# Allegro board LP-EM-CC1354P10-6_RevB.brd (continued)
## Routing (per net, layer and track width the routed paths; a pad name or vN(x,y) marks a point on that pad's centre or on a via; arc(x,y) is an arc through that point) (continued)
DIO35: length 25.9
  TOP w0.15: v1(30.61,49.53) 30.61,49.46 30.75,49.32 U1.11 ; v1(33.22,48.96) 33.41,48.96 33.7,49.25 34.38,49.25 34.48,49.15 35.61,49.15 35.63,49.12 35.99,49.12 36.06,49.2 R18.2
  L3 w0.15: P5.2 48.26,40.76 47.7,41.32 47.22,41.32 40.87,47.68 38.32,47.68 37.88,48.12 35.38,48.12 34.66,48.84 34.66,48.84 34.41,49.09 34.41,49.09 34.3,49.2 33.46,49.2 v1(33.22,48.96)
  BOTTOM w0.15: v1(33.22,48.96) 31.18,48.96 v1(30.61,49.53)
DIO35_RF_SUB1G: length 19.5
  TOP w0.15: v1(36.75,48.67) 36.75,48.8 36.9,48.95 R18.1 ; U2.6 v1(29.33,38.35)
  L3 w0.15: v1(29.33,38.35) 30.1,38.35 30.52,38.76 30.53,38.76 30.76,38.99 30.76,39 30.78,39.03 30.78,39.36 31.47,40.05 31.47,41.65 32.98,43.15 32.98,45.32 33.04,45.38 33.04,46.71 32.31,47.44 32.31,47.47 32.3,47.48 32.3,49.07 33.07,49.85 34.5,49.85 34.66,49.69 34.66,49.69 35.23,49.12 36.3,49.12 v1(36.75,48.67)
DIO36_FLASH_MOSI: length 79.9
  TOP w0.15: U3.5 35.45,71.43 v1(37.67,71.43) ; U1.22 34.04,51.6 34.22,51.78 35.24,51.78 35.34,51.88 38.17,51.88 38.23,51.82 38.26,51.82 38.38,51.69 38.74,51.69 38.86,51.82 40.11,51.82 40.65,51.28 41.4,51.28 41.67,51.55 v1(41.7,51.55) 41.7,58.8 v1(41.9,59)
  L3 w0.15: v1(41.9,59) 37.85,63.05 33.93,63.05 30.3,66.68 30.3,68.4 31.2,69.3 38.88,69.3 39.9,70.32 39.9,71.01 39.46,71.45 38.35,71.45 38.32,71.43 v1(37.67,71.43) ; v1(41.7,51.55) 41.67,51.53 41.67,51.25 41.57,51.15 41.57,49.1 47.85,42.82 49.25,42.82 50.67,41.4 50.67,39.22 49.8,38.35 49.8,34.93 48.95,34.07 45.6,34.07 44.42,35.25 44.42,36.68 P5.3
DIO37_FLASH_MISO: length 56
  TOP w0.15: U3.2 v1(32.27,72.65) ; v1(40.85,51.7) 40.44,52.11 40.34,52.11 40.33,52.12 v1(38.56,52.12) 38.36,52.12 38.3,52.18 35.22,52.18 35.12,52.07 34.09,52.07 34.02,52 U1.23
  L3 w0.15: v1(38.56,52.12) 38.47,52.2 38.47,52.26 38.35,52.38 38.35,52.7 38.46,52.81 38.46,52.86 38.47,52.87 38.52,52.92 38.52,55.53 36.48,57.57 35.55,57.57 33.57,59.55 33.57,59.55 27.6,65.53 27.6,69.53 30.72,72.65 v1(32.27,72.65) ; v1(40.85,51.7) 40.92,51.62 40.92,48.9 47.6,42.22 49,42.22 50.07,41.15 50.07,39.47 48.58,37.98 P5.4
DIO38_FLASH_CS: length 66.3
  TOP w0.15: v1(31.22,73.15) R24.1 U3.1 ; U1.24 35.02,52.4 35.09,52.47 38.31,52.47 38.38,52.54 38.79,52.54 38.88,52.62 38.88,52.62 v1(38.89,52.63) 39.07,52.45 40.42,52.45 40.46,52.41 40.99,52.41 41.05,52.35 v1(41.22,52.35)
  L3 w0.15: v1(31.22,73.15) 32.38,73.15 32.7,72.83 32.7,72.47 32.41,72.19 30.69,72.19 27.9,69.4 27.9,65.65 33.88,59.68 33.88,59.67 35.67,57.88 36.61,57.88 38.89,55.59 v1(38.89,52.63) ; v1(41.22,52.35) 41.22,52.2 41.21,52.19 41.21,52.16 41.27,52.1 41.27,48.97 47.72,42.53 49.12,42.53 50.38,41.28 50.38,39.35 49.47,38.45 49.47,35.03 48.82,34.38 46.45,34.38 45.72,35.1 P5.5
DIO39_FLASH_SCLK: length 70.8
  TOP w0.15: U3.6 35.88,72.15 36.02,72 v1(36.02,71.95) ; U1.25 38.21,52.8 38.49,53.07 39.08,53.07 39.23,52.93 40.55,52.93 v1(40.64,52.84) 40.72,52.93 40.72,57.65 40.55,57.82 v1(40.55,59.2)
  L3 w0.15: v1(40.64,52.84) 40.52,52.72 40.52,51.98 40.51,51.96 40.51,51.96 40.42,51.87 40.42,51.52 40.52,51.42 40.52,48.87 47.47,41.93 48.88,41.93 49.77,41.03 49.77,39.6 49.2,39.03 47.38,39.03 47.07,38.72 47.07,36.9 48.26,35.71 P5.6 ; v1(40.55,59.2) 40.55,59.65 37.45,62.75 33.8,62.75 30,66.55 30,68.53 31.07,69.6 37.62,69.6 38.22,70.2 39.35,70.2 39.6,70.45 39.6,70.88 39.33,71.15 38.47,71.15 38.33,71.01 37.86,71.01 37.85,71 37.5,71 37.49,71.01 36.17,71.01 36.02,71.15 v1(36.02,71.95)
DIO40: length 39.4
  TOP w0.15: R10.2 R8.2 39.17,69.95 v1(39.17,70.71) ; U1.41 29.55,57.2 30.6,58.25 30.6,58.72 31.15,59.28 31.15,59.3 31.4,59.55 32.52,59.55 33.8,60.82 v1(34.42,60.82)
  L3 w0.15: v1(39.17,70.71) 37.98,70.71 37.98,70.7 36,70.7 35.2,69.9 30.95,69.9 29.7,68.65 29.7,66.43 33.68,62.45 37.32,62.45 38.55,61.22 38.55,59.9 38.3,59.65 37.01,59.65 36.56,60.1 36.52,60.1 36.15,60.47 34.77,60.47 v1(34.42,60.82)
DIO41: length 42.9
  TOP w0.15: v1(32.77,55.68) 31.95,55.68 31.82,55.8 29.36,55.8 29.15,56.01 U1.42
  L3 w0.15: v1(32.77,55.68) 34.92,55.68 35.38,55.22 35.38,54.03 36.97,52.43 36.97,50.48 38.85,48.6 39.48,48.6 39.9,49.02 39.9,51.13 39.79,51.24 39.79,52.08 39.91,52.21 39.91,53.14 40.42,53.65 41.07,53.65 43.32,51.4 43.32,49.35 48.47,44.2 52.25,44.2 53.12,45.07 53.12,47.09 J2.18
DIO42: length 46.7
  TOP w0.15: U1.43 28.75,55.92 29.17,55.5 31.07,55.5 v1(31.2,55.38)
  L3 w0.15: v1(31.2,55.38) 31.32,55.25 32.94,55.25 33.03,55.34 34.81,55.34 35.07,55.07 35.07,53.9 36.67,52.3 36.67,50.35 38.73,48.3 39.6,48.3 40.2,48.9 40.2,51.25 40.12,51.33 40.12,51.4 40.09,51.44 40.09,51.96 40.21,52.08 40.21,53.01 40.55,53.35 40.95,53.35 43.02,51.28 43.02,49.22 48.35,43.9 52.38,43.9 53.42,44.95 53.42,49.18 52.07,50.53 J2.16
DIO43: length 27.8
  TOP w0.15: U1.44 28.35,55.88 28.6,55.63 v1(28.6,55.45)
  L3 w0.15: v1(28.6,55.45) 28.6,55.5 28.42,55.68 27.77,55.68 27.52,55.43 27.52,55.42 27.27,55.17 27.27,50.18 25.75,48.65 25,48.65 24,49.65 22.79,49.65 21.64,48.5 9.23,48.5 J1.18
DIO44: length 28.5
  TOP w0.15: v1(27.95,55.25) U1.45
  L3 w0.15: v1(27.95,55.25) 27.6,54.9 27.6,49.3 26.05,47.75 24.7,47.75 23.63,48.82 22.75,48.82 22.7,48.77 22.68,48.77 19.41,45.5 8.97,45.5 J1.20
DIO45: length 61.1
  TOP w0.15: v1(34.11,56.11) 34.92,56.93 36.1,56.93 v1(37.7,58.53) ; R19.1 25.07,56.3 25.95,56.3 v1(25.97,56.28) 26.07,56.28 26.65,55.7 27.23,55.7 27.55,56.02 U1.46
  L3 w0.15: v1(25.97,56.28) 26.75,57.05 33.17,57.05 v1(34.11,56.11) ; J2.7 41.97,68.4 31.57,68.4 31.2,68.03 31.2,67.05 34.3,63.95 38.4,63.95 42.33,60.03 42.92,59.43 42.92,58.57 42.3,57.95 38.27,57.95 v1(37.7,58.53)
DIO46: length 81.4
  TOP w0.15: v1(19.4,58.1) R20.1 19.52,57.45 19.52,56.5 18.85,55.82 18.85,52.97 19.25,52.57 22.1,52.57 22.7,51.97 23.58,51.97 23.6,52 U1.58
  L3 w0.15: v1(19.4,58.1) 19.52,58.23 19.52,63.15 16.15,66.52 16.15,71.47 17.17,72.5 23.47,72.5 25.95,74.97 28.88,74.97 29.49,74.37 30.76,74.37 30.86,74.46 34.26,74.46 34.54,74.18 39.45,74.18 40.17,74.9 41.6,74.9 42.88,73.62 42.88,70.7 43.55,70.02 45.09,70.02 46.38,71.31 46.38,74.43 47.49,75.54 49.06,75.54 49.48,75.12 49.48,74.76 48.35,73.63 48.35,67.97 49.53,66.79 J2.3
DIO47: length 79.5
  TOP w0.15: U1.59 25.32,51.6 25.3,51.62 23.65,51.62 23.6,51.68 22.57,51.68 21.97,52.28 19.1,52.28 18.55,52.82 18.55,55.95 18.67,56.07 R21.1 18.67,56.82 18.82,56.97 v1(18.95,56.97)
  L3 w0.15: J2.1 49.53,74.39 49.78,74.64 49.78,75.24 49.19,75.84 47.15,75.84 44.89,73.58 44.89,70.72 44.51,70.34 43.67,70.34 43.17,70.83 43.17,73.97 41.9,75.25 40.1,75.25 40.05,75.2 40.05,75.2 39.32,74.47 34.67,74.47 34.38,74.76 30.73,74.76 30.63,74.66 29.61,74.66 28.75,75.53 26.07,75.53 25.82,75.28 25.82,75.28 23.35,72.8 17.05,72.8 15.85,71.6 15.85,66.4 18.95,63.3 v1(18.95,56.97)
LP_RESET: length 17
  TOP w0.15: R10.1 R11.1 v1(42.25,67.5) ; v1(50.95,59.35) 51.02,59.35 J2.10
  L3 w0.15: v1(50.95,59.35) 50.77,59.53 48.44,59.53 42.25,65.72 v1(42.25,67.5)
RX_TX: length 15.2
  TOP w0.15: U1.7 29.15,49.18 28.88,49.45 v1(28.88,49.53)
  TOP w0.3: C56.2 26.28,44.62 v1(26.29,44.61) 26.29,45.07 L40.1 ; 24.3,47.65 23.8,47.65 23.7,47.75 v1(23.65,47.75) ; 24.3,47.65 C11.2 ; 24.3,47.65 L12.1
  L3 w0.3: v1(28.88,49.53) 28.88,48.75 27.77,47.65 ; 27.77,47.65 27.16,47.03 24.41,47.03 23.7,47.75 v1(23.65,47.75) ; 27.77,47.65 27.77,45.1 27.28,44.61 v1(26.29,44.61)
WMCU_RESET: length 95.4
  TOP w0.15: v1(29.27,73.97) 29.27,76.93 29.42,77.07 v1(29.42,77.15) ; v1(49.06,74.94) P6.10 49.06,78.63 50.15,79.72 51.43,79.72 52.52,80.82 52.52,81.65 52.12,82.05 CR2.2 ; U1.49 25.13,55.6 24.7,56.03 24.68,56.03 24.18,56.53 R1.1 23.4,56.53 C54.1 23.1,56.32 22.7,56.72 21.57,56.72 v1(20.55,57.75) ; R9.2 37.95,70.15 37.95,70.5 38.56,71.11 38.98,71.11 39,71.13 39.35,71.13 39.6,70.88 39.6,70.8 39.75,70.65 41.5,70.65 R11.2 42.32,69.83 v1(43.13,69.83)
  L3 w0.15: v1(49.06,74.94) 48.76,75.24 47.61,75.24 46.96,74.6 46.96,70.39 46.3,69.72 43.25,69.72 v1(43.13,69.83) 42.57,70.39 42.57,73.5 41.47,74.6 40.3,74.6 39.57,73.88 34.42,73.88 34.13,74.16 33.81,74.16 33.63,73.97 v1(29.27,73.97) 28.57,74.68 26.07,74.68 23.6,72.2 17.3,72.2 16.45,71.35 16.45,66.65 20.44,62.66 20.44,57.86 v1(20.55,57.75) ; J4.10 30.51,87.01 29.38,85.88 29.38,78.97 29.42,78.93 v1(29.42,77.15)
WMCU_RXD: length 91.2
  TOP w0.15: v1(26.38,77.15) v1(26.38,73.95) ; v1(37.45,53.3) 37.35,53.2 U1.26
  L3 w0.15: J4.14 25.45,87.01 26.5,85.97 26.5,77.28 v1(26.38,77.15) 25.57,77.15 25.2,76.78 25.2,76.78 22.72,74.3 16.42,74.3 15.9,73.78 9.22,73.78 7.38,71.93 7.38,68.03 6.71,67.35 5.85,67.35 4.98,66.48 4.98,65.36 5.77,64.57 5.78,64.57 6.33,64.02 J1.5 ; v1(26.38,73.95) 26.2,73.95 23.85,71.6 17.55,71.6 17.05,71.1 17.05,66.9 21.55,62.4 29.45,62.4 32.07,59.78 32.08,59.78 32.67,59.18 32.67,59.17 35.17,56.68 36.11,56.68 37.45,55.33 v1(37.45,53.3)
WMCU_SWO: length 108.4
  TOP w0.15: v1(34.88,59.4) 33.9,59.4 31.55,57.05 U1.36 ; v1(28.3,73.97) 28.3,76.97 28.42,77.1 v1(28.42,77.22) ; CR3.5 45.11,82.57 44.8,82.27 44.8,79.78 43.27,78.25 43.27,76.97 v1(40.47,74.18)
  L3 w0.15: 34.42,72.97 34.01,73.39 33.81,73.39 33.53,73.68 29.58,73.68 29.38,73.48 29.17,73.48 29.1,73.55 28.67,73.97 v1(28.3,73.97) ; 34.42,72.97 34.42,72.95 33.36,71.88 30.81,71.88 28.2,69.28 28.2,65.78 34.17,59.8 34.17,59.8 34.57,59.4 v1(34.88,59.4) 35.27,59.4 35.37,59.3 35.85,59.3 37.5,57.65 42.43,57.65 43.22,58.45 43.22,59.55 42.45,60.32 42.45,60.32 38.53,64.25 34.43,64.25 31.5,67.18 31.5,67.9 31.7,68.1 38.6,68.1 38.63,68.07 38.92,68.07 48.7,58.3 J2.9 ; 34.42,72.97 35,73.55 35.32,73.55 35.35,73.57 39.88,73.57 v1(40.47,74.18) ; v1(28.42,77.22) 28.27,77.38 28.27,84.18 J4.11
WMCU_TCK: length 68.7
  TOP w0.15: CR2.6 49.9,82.05 v1(49.65,81.8) ; v1(34.7,71) 34.32,70.62 R5.2 ; v1(37.7,60.88) 37.7,60.3 35.54,58.14 34.34,58.14 33.26,57.06 33.26,56.59 33.12,56.45 U1.33 ; v1(41.2,72.93) 41.2,72.98 43.25,75.03 44.63,75.03 45.25,75.64 P6.4 45.25,78.53 45.77,79.05 46.57,79.05 47.47,79.95 47.9,79.95 48.15,80.2 48.15,80.63 48.3,80.78 v1(48.3,81.23)
  L3 w0.15: J4.6 36.76,85.85 38.88,85.85 39.19,85.54 46.51,85.54 48.3,83.75 v1(48.3,81.23) 49.07,81.23 v1(49.65,81.8) ; v1(41.2,72.93) 40.5,72.93 39.75,72.18 36.83,72.18 36.33,72.68 35.72,72.68 34.7,71.65 v1(34.7,71) 34.2,70.5 30.7,70.5 29.1,68.9 29.1,66.18 33.43,61.85 36.85,61.85 37.7,61 v1(37.7,60.88)
WMCU_TMS: length 74
  TOP w0.15: CR2.7 50.15,81.25 v1(49.82,81.25) ; v1(40.95,72) 40.95,72.05 40.62,72.38 40.62,73.44 P6.2 43.98,78.1 45.22,79.35 46.45,79.35 47.39,80.29 47.64,80.29 v1(47.72,80.38) ; U1.32 33.6,56.97 34.47,57.84 35.67,57.84 35.75,57.93 35.8,57.93 37.95,60.07 v1(38.12,60.07) ; R4.2 35.8,70.07 v1(35.22,70.65)
  L3 w0.15: v1(49.82,81.25) 49.41,80.84 48.74,80.84 48.27,80.38 v1(47.72,80.38) 47.72,80.85 47.88,81 47.88,81.83 47.96,81.92 47.96,83.67 46.4,85.23 43.2,85.23 41.4,83.43 40.22,83.43 39.42,84.23 39.42,84.88 38.75,85.55 34.52,85.55 J4.8 ; v1(38.12,60.07) 38.17,60.12 38.17,61.18 37.2,62.15 33.55,62.15 29.4,66.3 29.4,68.78 30.82,70.2 34.77,70.2 v1(35.22,70.65) 35.22,71.75 35.85,72.38 36.2,72.38 36.7,71.88 39.88,71.88 40.35,72.35 40.6,72.35 v1(40.95,72)
WMCU_TXD: length 97
  TOP w0.15: v1(27.35,77.15) 27.35,74 v1(27.3,73.95) ; v1(36.97,53.7) 36.88,53.6 U1.27
  L3 w0.15: J4.12 26.8,85.84 26.8,83.75 27.47,83.07 27.47,77.28 v1(27.35,77.15) 26.92,76.72 25.57,76.72 25.32,76.47 25.32,76.47 22.85,74 16.55,74 16.02,73.47 9.35,73.47 7.68,71.81 7.68,67.63 7.02,66.97 5.9,66.97 5.28,66.35 5.28,65.49 5.9,64.87 6.88,64.87 7.52,64.23 7.52,62.82 7.52,62.82 7.52,62.03 J1.7 ; v1(36.97,53.7) 36.97,55.38 35.98,56.38 35.05,56.38 32.38,59.05 32.38,59.05 31.95,59.47 31.95,59.47 29.32,62.1 21.42,62.1 16.75,66.77 16.75,71.22 17.42,71.9 23.72,71.9 26.2,74.38 26.55,74.38 26.77,74.16 27.15,74.16 27.3,74.01 v1(27.3,73.95)
WMCU_VDD: length 146.6
  TOP w0.15: v1(4.22,47.62) 3.65,47.05 R3.2 ; R2.2 v1(4.18,44.93)
  TOP w0.25: R25.2 33.17,74.53 v1(32.52,75.18) ; R24.2 31.65,73.95 R23.2 v1(30.47,75.05) ; R22.2 v1(38.42,75)
  TOP w0.3: v1(46.12,80.43) CR3.8 ; v1(22.92,60.5) 22.92,60.5 23,60.43 FL1.2 ; v1(43.92,70.82) 43.92,72.89 P6.1 ; v1(51.15,80.65) 51.15,81.4
  L3 w0.15: 4.22,44.97 v1(4.18,44.93)
  L3 w0.5: v1(46.12,80.43) 46.22,80.32 46.22,76.18 ; 51.15,76.2 v1(51.15,80.65) ; 22.89,85.94 J4.16 23.97,87.01 ; v1(43.92,70.82) 43.92,76.18 ; v1(38.42,75) 38.42,76.12 38.38,76.18
  L3 w1: 23.27,82.95 23.52,82.7 v1(23.52,76.18) v1(22.77,76.18) 10.45,76.18 6.33,72.06 J1.1 5.94,68.46 4.22,66.75 4.1,48.55 4.1,47.75 v1(4.22,47.62) 4.22,44.97 ; P3.1 52.34,35.44 54.07,37.17 54.07,43.55 54.92,44.4 54.92,51.82 54.07,52.67 54.07,70.2 51.17,73.1 51.17,76.18 50.7,76.65 46.7,76.65 46.22,76.18 v1(31.8,76.18) v1(31,76.18)
  vias: v1(22.52,60.9) v1(23.17,60.88) v1(23.6,60.6)
XDS_BOARDID_SCL: length 13.6
  TOP w0.15: v1(11.95,83.72) U4.1
  L3 w0.15: J4.15 22.22,84.48 19.88,82.12 13.57,82.12 11.98,83.72 v1(11.95,83.72)
XDS_BOARDID_SDA: length 8.5
  TOP w0.15: v1(13.85,83.72) U4.3
  L3 w0.15: v1(13.85,83.72) 14.65,82.93 18.8,82.93 J4.17
XDS_GPIO1: length 81.3
  TOP w0.15: R19.2 v1(25.26,57.11) ; CR3.1 v1(46.82,81.1)
  L3 w0.15: 38.14,84.47 39.48,83.12 43.25,83.12 44,83.88 44.43,83.88 44.44,83.89 44.76,83.89 44.77,83.88 46.7,83.88 47.38,83.2 47.38,82.78 46.82,82.23 v1(46.82,81.1) ; 38.14,84.47 36.79,83.12 32.27,83.12 32.17,83.02 31.85,83.02 31.35,82.52 31.35,81.93 31,81.58 31,78.08 29.35,76.43 25.7,76.43 25.45,76.18 25.45,76.18 22.97,73.7 16.67,73.7 16.15,73.18 9.47,73.18 8.77,72.48 8.77,71.37 11.85,68.3 11.85,57.33 12.94,56.24 19.91,56.24 20.32,56.65 v1(20.5,56.65) ; 38.14,84.47 J4.3
  BOTTOM w0.15: v1(20.5,56.65) 21.96,56.65 22.31,56.3 24.07,56.3 24.88,57.11 v1(25.26,57.11)
XDS_GPIO2: length 64.3
  TOP w0.15: R20.2 18.62,57.57 v1(18.25,57.95) ; v1(47.5,82.07) CR3.2 ; v1(30.47,81.35) 30.52,81.39 31.81,81.39 v1(31.82,81.38)
  L3 w0.15: v1(47.5,82.07) 47.5,81.97 47.57,81.9 47.57,81.12 47.12,80.67 46.65,80.67 46.4,80.92 46.4,81 46.02,81.38 v1(31.82,81.38) 31.6,81.15 31.6,77.83 29.6,75.82 25.95,75.82 25.7,75.57 25.7,75.57 23.22,73.1 16.92,73.1 15.55,71.72 15.55,66.27 18.38,63.45 18.38,58.07 v1(18.25,57.95) ; v1(30.47,81.35) 30.47,81.48 30.92,81.93 30.92,82.63 30.94,82.65 30.94,82.92 31.35,83.32 32.05,83.32 32.15,83.43 34.54,83.43 J4.5
XDS_GPIO3: length 59.4
  TOP w0.15: R21.2 18.1,56.44 18.1,56.9 v1(18,57) ; v1(46.82,83.05) CR3.3 ; v1(30.47,82.32) v1(31.82,82.32)
  L3 w0.15: 31.82,82.25 32.4,82.82 46.07,82.82 46.3,83.05 v1(46.82,83.05) ; 31.82,82.25 31.82,81.98 31.3,81.45 31.3,77.95 29.47,76.12 25.82,76.12 25.57,75.88 23.1,73.4 16.8,73.4 15.25,71.85 15.25,66.15 16.99,64.41 16.99,58.34 17,58.33 17,57.57 17.62,56.95 17.95,56.95 v1(18,57) ; 31.82,82.25 v1(31.82,82.32) ; J4.9 30.51,82.37 v1(30.47,82.32)
N3099875: length 2.9
  TOP w0.2: 25.92,47.65 26.75,48.48 U1.1
  TOP w0.25: L11.1 25.92,47.65
  TOP w0.3: L11.1 25.74,47.65 L12.2 25.28,47.25 24.88,46.85 C13.1
N3099951: length 1.2
  TOP w0.3: 24.4,45.96 24.41,45.95 L13.2 ; 24.4,45.96 C13.2 ; 24.4,45.96 24.4,45.95 L14.1
N3100073: length 1.5
  TOP w0.3: L15.1 23.79,43.96 C14.2 23.79,45.34 L14.2
N3100081: length 1.3
  TOP w0.3: C16.1 23.81,42.11 C15.2 23.8,42.76 L15.2
N3100105: length 5.9
  TOP w0.3: J3.1 33.43,30.35 C17.1
N3100141: length 3.2
  TOP w0.2: 26.25,47.35 27.15,48.25 U1.2
  TOP w0.25: 26.25,47.35 L11.2
  TOP w0.3: L13.1 25.36,46.35 C12.2 26.25,47.24 L11.2
N3100321: length 5
  TOP w0.3: Z45.1 33,36.6 CR1.2 C17.2
N3100543: length 8.1
  TOP w0.2: U2.8 29.53,37.55
  TOP w0.3: C16.2 23.8,41.15 27.4,37.55 29.53,37.55
N3100575: length 1.6
  TOP w0.2: U2.5 29.79,38.94
  TOP w0.3: 29.79,38.94 C27.2
N3100757: length 1.2
  TOP w0.2: U1.3 27.55,47.7 L41.1
N3100925: length 1.2
  TOP w0.2: U1.4 27.95,47.7 L44.1
N3100985: length 5.3
  TOP w0.2: L34.1 29.65,47.05 29.42,47.05 28.35,48.12 U1.5
  TOP w0.3: L34.1 30.85,45.84 L35.2 31.74,44.95 C32.1
N3100993: length 3
  TOP w0.15: 32.05,31.7 C18.2
  TOP w0.3: Z1.1 32.05,31.7
N3100997: length 5.1
  TOP w0.15: 31.25,46.25 L34.2
  TOP w0.2: U1.6 28.75,48.25 29.55,47.45 30.05,47.45 31.25,46.25
  TOP w0.3: L36.1 32.12,45.38 C31.2 31.26,46.25 L34.2
N3101199: length 13.1
  TOP w0.15: C50.1 39.42,43.55 Y1.1 37.85,43.55 37.21,44.19 37.21,44.87 36.24,45.84 36.09,45.84 35.92,46.01 35.88,46.01 35.17,46.72 32.88,46.72 32.79,46.81 32.14,46.81 31.16,47.8 30.03,47.8 29.55,48.28 U1.8
N3101207: length 11.3
  TOP w0.15: U1.9 29.95,48.31 30.16,48.1 31.28,48.1 32.27,47.11 32.91,47.11 33,47.03 35.29,47.03 36.01,46.31 36.04,46.31 36.21,46.14 36.46,46.14 36.7,45.9 Y1.2 39.55,45.9 C51.1
N3101223: length 6.8
  TOP w0.15: U1.63 25.48,50 25.13,49.65 23.27,49.65 22.92,49.3 Y2.1 19.6,49.3 C52.1
N3101377: length 3.1
  TOP w0.3: 29.1,29.9 Z4.1 Z2.1 ; 29.1,29.9 Z3.2 ; 29.1,29.9 Z1.2
N3101433: length 1.7
  TOP w0.3: A1.1 Z2.2
  vias: v1(10.4,18) v1(10.4,13.11) v1(10.41,7.97) v1(10.41,2.97) v1(11.79,14.53) v1(11.79,4.48) v1(12.84,11.6) v1(12.83,1.6) v1(13.77,18) v1(14.82,13) v1(14.8,3) v1(15.89,8) v1(17.77,16.6) v1(17.84,11.6) v1(17.83,1.6) v1(18.77,18) v1(18.91,6.6) v1(19.8,3) v1(19.82,13) v1(20.89,8) v1(22.77,16.6) v1(22.85,11.6) v1(22.82,1.6) v1(23.77,18) v1(23.91,6.6) v1(24.8,3) v1(24.82,13) v1(25.89,8) v1(27.85,11.6) v1(27.82,1.6) v1(28.4,25.05) v1(28.4,20.05) v1(28.91,6.6) v1(29.8,21.55) v1(29.8,16.6) v1(29.8,3) v1(29.82,13) v1(30.89,8) v1(32.85,11.6) v1(32.82,1.6) v1(33.91,6.6) v1(34.8,3) v1(34.82,13) v1(35.89,8) v1(37.85,11.6) v1(37.82,1.6) v1(38.91,6.6) v1(39.8,3) v1(39.82,13) v1(40.89,8) v1(42.85,11.6) v1(42.82,1.6) v1(43.91,6.6) v1(44.8,3) v1(44.82,13) v1(46.4,9.56) v1(47.79,11.54) v1(47.79,6.61) v1(47.77,1.6)
N3101449: length 7
  TOP w0.15: C53.1 19.64,51.14 Y2.3 22.11,51.14 23.3,49.95 25,49.95 25.28,50.23 25.45,50.4 U1.62
N3101953: length 2
  TOP w0.15: 31.98,38.75 31.98,38.75 31.98,38.75 ; 31.98,38.75 U2.4
  TOP w0.3: C62.1 32.68,38.75 ; 32.68,38.75 31.98,38.75 ; 32.68,38.75 33.48,38.75 Z44.1
N3109894: length 21.5
  TOP w0.15: v1(35.8,67.5) R4.1
  L3 w0.15: J2.13 46.7,56.05 46.7,57.78 44.42,60.05 42.95,61.53 42.95,61.53 39,65.47 37.9,65.47 35.87,67.5 v1(35.8,67.5)
N3109960: length 25.2
  TOP w0.15: v1(34.32,67.5) R5.1
  L3 w0.15: J2.15 46.1,54.11 46.1,57.95 44.12,59.93 44.12,59.93 42.83,61.22 38.88,65.18 37.77,65.18 37.7,65.25 36.62,65.25 34.36,67.5 v1(34.32,67.5)
N3110034: length 28.7
  TOP w0.15: v1(33.27,67.53) 32.83,67.97 R6.1
  L3 w0.15: J2.17 45.1,52.57 45.1,58.52 43.82,59.8 43.82,59.8 42.7,60.93 38.75,64.88 35.92,64.88 v1(33.27,67.53)
N3110086: length 32.6
  TOP w0.15: v1(32,67.57) 31.7,67.57 31.35,67.93 R7.1 ; v1(48.28,46.86) J2.19
  L3 w0.15: v1(32,67.57) 32,67.53 34.95,64.57 38.63,64.57 42.58,60.62 42.58,60.62 43.52,59.68 44.75,58.45 44.75,50.38 v1(48.28,46.86)
N3110356: length 2.1
  TOP w0.15: R15.2 22.88,68 P1.1
N3110380: length 2.1
  TOP w0.15: R14.2 21.85,70.52 21.84,70.53 P1.3
N3110768: length 1.3
  TOP w0.15: SW1.4 5.53,73.2 R12.1
N3110772: length 3.3
  TOP w0.15: R13.1 54.75,70.2 54.75,72.82 54.4,73.18 SW2.3
N3110876: length 1.4
  TOP w0.15: R14.1 24.67,70.52 CR4.2
N3110880: length 1.4
  TOP w0.15: R15.1 24.67,68 CR5.2
N3111246: length 2.9
  TOP w0.25: R25.1 35.57,74.38 35.97,73.97 C55.1 U3.8
N3111262: length 3.3
  TOP w0.15: R22.1 37.32,72.35 37.02,72.65 U3.7
N3111266: length 2.4
  TOP w0.15: U3.3 31.95,72.15 31.75,72.35 R23.1
N3254079: length 2.2
  TOP w0.25: U1.47 27.15,58.57 L1.2
N3281348: length 1.2
  TOP w0.15: U1.31 33.62,55.22 34.5,55.22 C9.1
N3492676: length 1.3
  TOP w0.3: L27.2 28.41,40.14 Z7.1 C27.1
N3492704: length 0.6
  TOP w0.3: Z7.2 Z8.1
N3493209: length 2.6
  TOP w0.3: C57.1 27.45,45.06 L40.2 27.47,45.09 L42.1 C58.1 27.42,46.43 L41.2
N3493257: length 2
  TOP w0.3: L43.1 C59.1 27.77,43.42 ; 27.77,43.42 27.45,43.75 C57.2 ; 27.77,43.42 28.1,43.75 L45.2
N3493329: length 1.3
  TOP w0.3: L27.1 C60.1 L43.2
N3493341: length 2.6
  TOP w0.3: L44.2 28.07,46.41 C58.2 L42.2 28.07,45.69 28.07,45.1 C61.1 L45.1
N3546372: length 3.2
  TOP w0.3: C33.1 30.56,44.41 R41.1 ; C33.1 30.62,44.59 30.9,44.87 L35.1 ; C33.1 31.08,43.94 C34.1 31.79,43.25 R42.1
N3546508: length 1.9
  TOP w0.3: 32.61,44.59 32.57,44.63 L36.2 ; 32.61,44.59 32.61,44.58 C35.1 32.87,44.28 L37.1 ; 32.61,44.59 32.18,44.59 C32.2
N3546612: length 1.5
  TOP w0.3: 33.69,43.46 34.07,43.08 34.07,43.07 34.72,42.42 34.75,42.42 L39.1
N3546624: length 1.7
  TOP w0.3: L39.2 34.74,41.81 C38.2 34.74,40.13 C39.1
N3546636: length 1.2
  TOP w0.3: C39.2 34.75,39.24 34.26,38.75 Z44.2
N3547384: length 1.4
  TOP w0.2: 31.9,37.55 U2.1
  TOP w0.3: 31.9,37.55 32.21,37.55 C63.1 32.24,37.48 32.66,37.06 32.66,37.05

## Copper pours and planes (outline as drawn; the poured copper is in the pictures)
GND on TOP: 0.5,87.99 0.65,88.34 1,88.49 57.5,88.49 57.85,88.34 58,87.99 58,81.6 57.74,80.1 57.01,78.76 55.8,75.3 57.01,71.84 57.74,70.5 58,69 58,26.55 29.75,26.55 29.75,31 32.35,31 32.35,29.7 36.07,29.7 37.04,28.2 38.72,27.62 41.45,30.35 38.72,33.08 37.04,32.5 36.07,31 33.65,31 33.65,37.03 32.6,38.07 31.07,38.07 31.07,36.95 31.88,36.95 32.35,36.47 32.35,32.4 28.45,32.4 28.45,26.55 0.5,26.55 0.5,69 0.76,70.5 1.49,71.84 2.7,75.3 1.49,78.76 0.76,80.1 0.5,81.6 ; 11 cut-outs
VDDR on L3: 29.2,59.57 29.2,58.3 29.42,58.07 29.8,58.07 29.9,58.18 29.9,59.35 29.6,59.65 29.27,59.65
VDDS on L3: 24.32,58 22.75,58 22.4,57.65 22.4,56.97 23.12,56.25 23.82,56.25 24.45,56.88 24.45,57.88
(no net) on TOP: 29.32,58.22 29.92,58.22 29.92,59.55 29.02,60.45 28.12,60.45 28.12,59.32 29.32,59.32
(no net) on TOP: 22.3,59 22.3,56.93 23.85,56.93 23.85,59
WMCU_VDD on TOP: 22.3,61.1 22.3,59.2 23.85,59.2 23.85,61.1
WMCU_VDD on BOTTOM: 22.27,75.25 22.27,60.32 23.88,60.32 23.88,75.25
WMCU_VDD on BOTTOM: 22.27,76.4 22.27,74.82 32.77,74.82 32.77,76.4
WMCU_VDD on L3: 22.3,61.1 22.3,60.28 23.85,60.28 23.85,61.1
WMCU_VDD on L3: 22.9,87.32 23.62,87.32 24.42,87.25 24.42,83.62 23.22,82.42 22.77,82.98 22.62,85.98 22.17,87.12
N3101433 on TOP (solid shape): 30.1,16.3 12.1,16.3 12.1,13.3 48.1,13.3 48.1,6.3 12.1,6.3 12.1,3.3 48.1,3.3 48.1,1.3 10.1,1.3 10.1,8.3 46.1,8.3 46.1,11.3 10.1,11.3 10.1,18.3 28.1,18.3 28.1,25.3 30.1,25.3
N3101433 on BOTTOM (solid shape): 30.1,16.3 12.1,16.3 12.1,13.3 48.1,13.3 48.1,6.3 12.1,6.3 12.1,3.3 48.1,3.3 48.1,1.3 10.1,1.3 10.1,8.3 46.1,8.3 46.1,11.3 10.1,11.3 10.1,18.3 28.1,18.3 28.1,25.3 30.1,25.3

Small or netless copper shapes (teardrops, artwork), in the pictures only: 140 on TOP, 10 on BOTTOM, 1 on L2, 176 on L3

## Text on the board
Ref Des/Silkscreen Bottom: J1 | 1 | 10 | 21 | 30 | J3 | J4 | 31 | 40 | 11 | 20 | J2 | DIO23 | DIO22 | DIO24 | DIO12 | DIO13 | DIO26 | DIO43 | DIO44 | DIO25 | DIO27 | DIO28 | DIO29 | DIO30 | GND | DIO3 | DIO34 | DIO36 | DIO38 | DIO35 | DIO37 | DIO39 | DIO46 | DIO20 | DIO18 | BPRST | DIO47 | DIO45 | DIO15 | DIO9 | DIO8 | DIO14 | DIO19 | DIO11 | LPRST | DIO42 | DIO41 | DIO10 | DIO21 | DIO4 | DIO5 | TMS | TCK | DIO16 | DIO17
User.Comments: Rev. B | Milling tool 2.0 mm TYP | MCU088 | RED | BOTTOM LAYER
Ref Des/Silkscreen Top: U4 | Y2 | U3 | DIO23 | DIO12 | DIO13 | DIO22 | DIO24 | J1 | DIO15 | BTN-1 | 10 | 1 | 21 | 30 | J3 | DIO25 | DIO26 | DIO27 | DIO28 | DIO29 | DIO30 | DIO43 | DIO44 | 2 | Red  : DIO6 | Green: DIO7 | CC-ANTENNA-DK | Mount for: | BP  LP | LP-EM-CC1354P10-6 | Rev: B   MCU088 | DIO47 | DIO46 | DIO20 | DIO45 | DIO18 | BPRST | JTAG | J4 | 40 | 31 | 20 | 11 | J2 | DIO19 | DIO11 | DIO14 | LPRST | DIO9 | DIO8 | DIO42 | DIO41 | DIO4 | DIO21 | DIO5 | DIO10 | DIO16 | DIO17 | TMS | TCK | Extension | LEDs | GND | 5V | 3V3 | RXD | TXD | SWO | nRST | GPIO3 | TDI | TDO | GPIO2 | R9 | GPIO1 | R8 | R10 | R11 | BTN-2
XSECTION_CHART: L1: TOP CONDUCTOR - COPPER + PLATING 0.035 MM | *  DIELECTRIC - FR-4 0.175 MM (TOP PRIORITY,  AFTER PRESS) | L2: L2 PLANE - COPPER 0.035 MM | *  DIELECTRIC - FR-4 1.11 MM | L3: L3 PLANE - COPPER 0.035 MM | *  DIELECTRIC - FR-4 0.175 MM | L4: BOTTOM CONDUCTOR - COPPER + PLATING 0.035 MM | DESIGN CROSS SECTION CHART | ___________________________ | TOTAL THICKNESS 1.6 MM
PAGE_OUTLINE: LP-EM-CC1354P10-6
User.27: FIGURE | FINISHED_SIZE | 0.2 | 1.05 | 1.1 | 3.2 | 0.899 | DRILL CHART: TOP to BOTTOM | ALL UNITS ARE IN MILLIMETERS | PLATED | NON-PLATED | QTY | 1022 | 82 | 1 | 4 | 2
